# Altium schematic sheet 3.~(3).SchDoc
size 420 x 297 mm
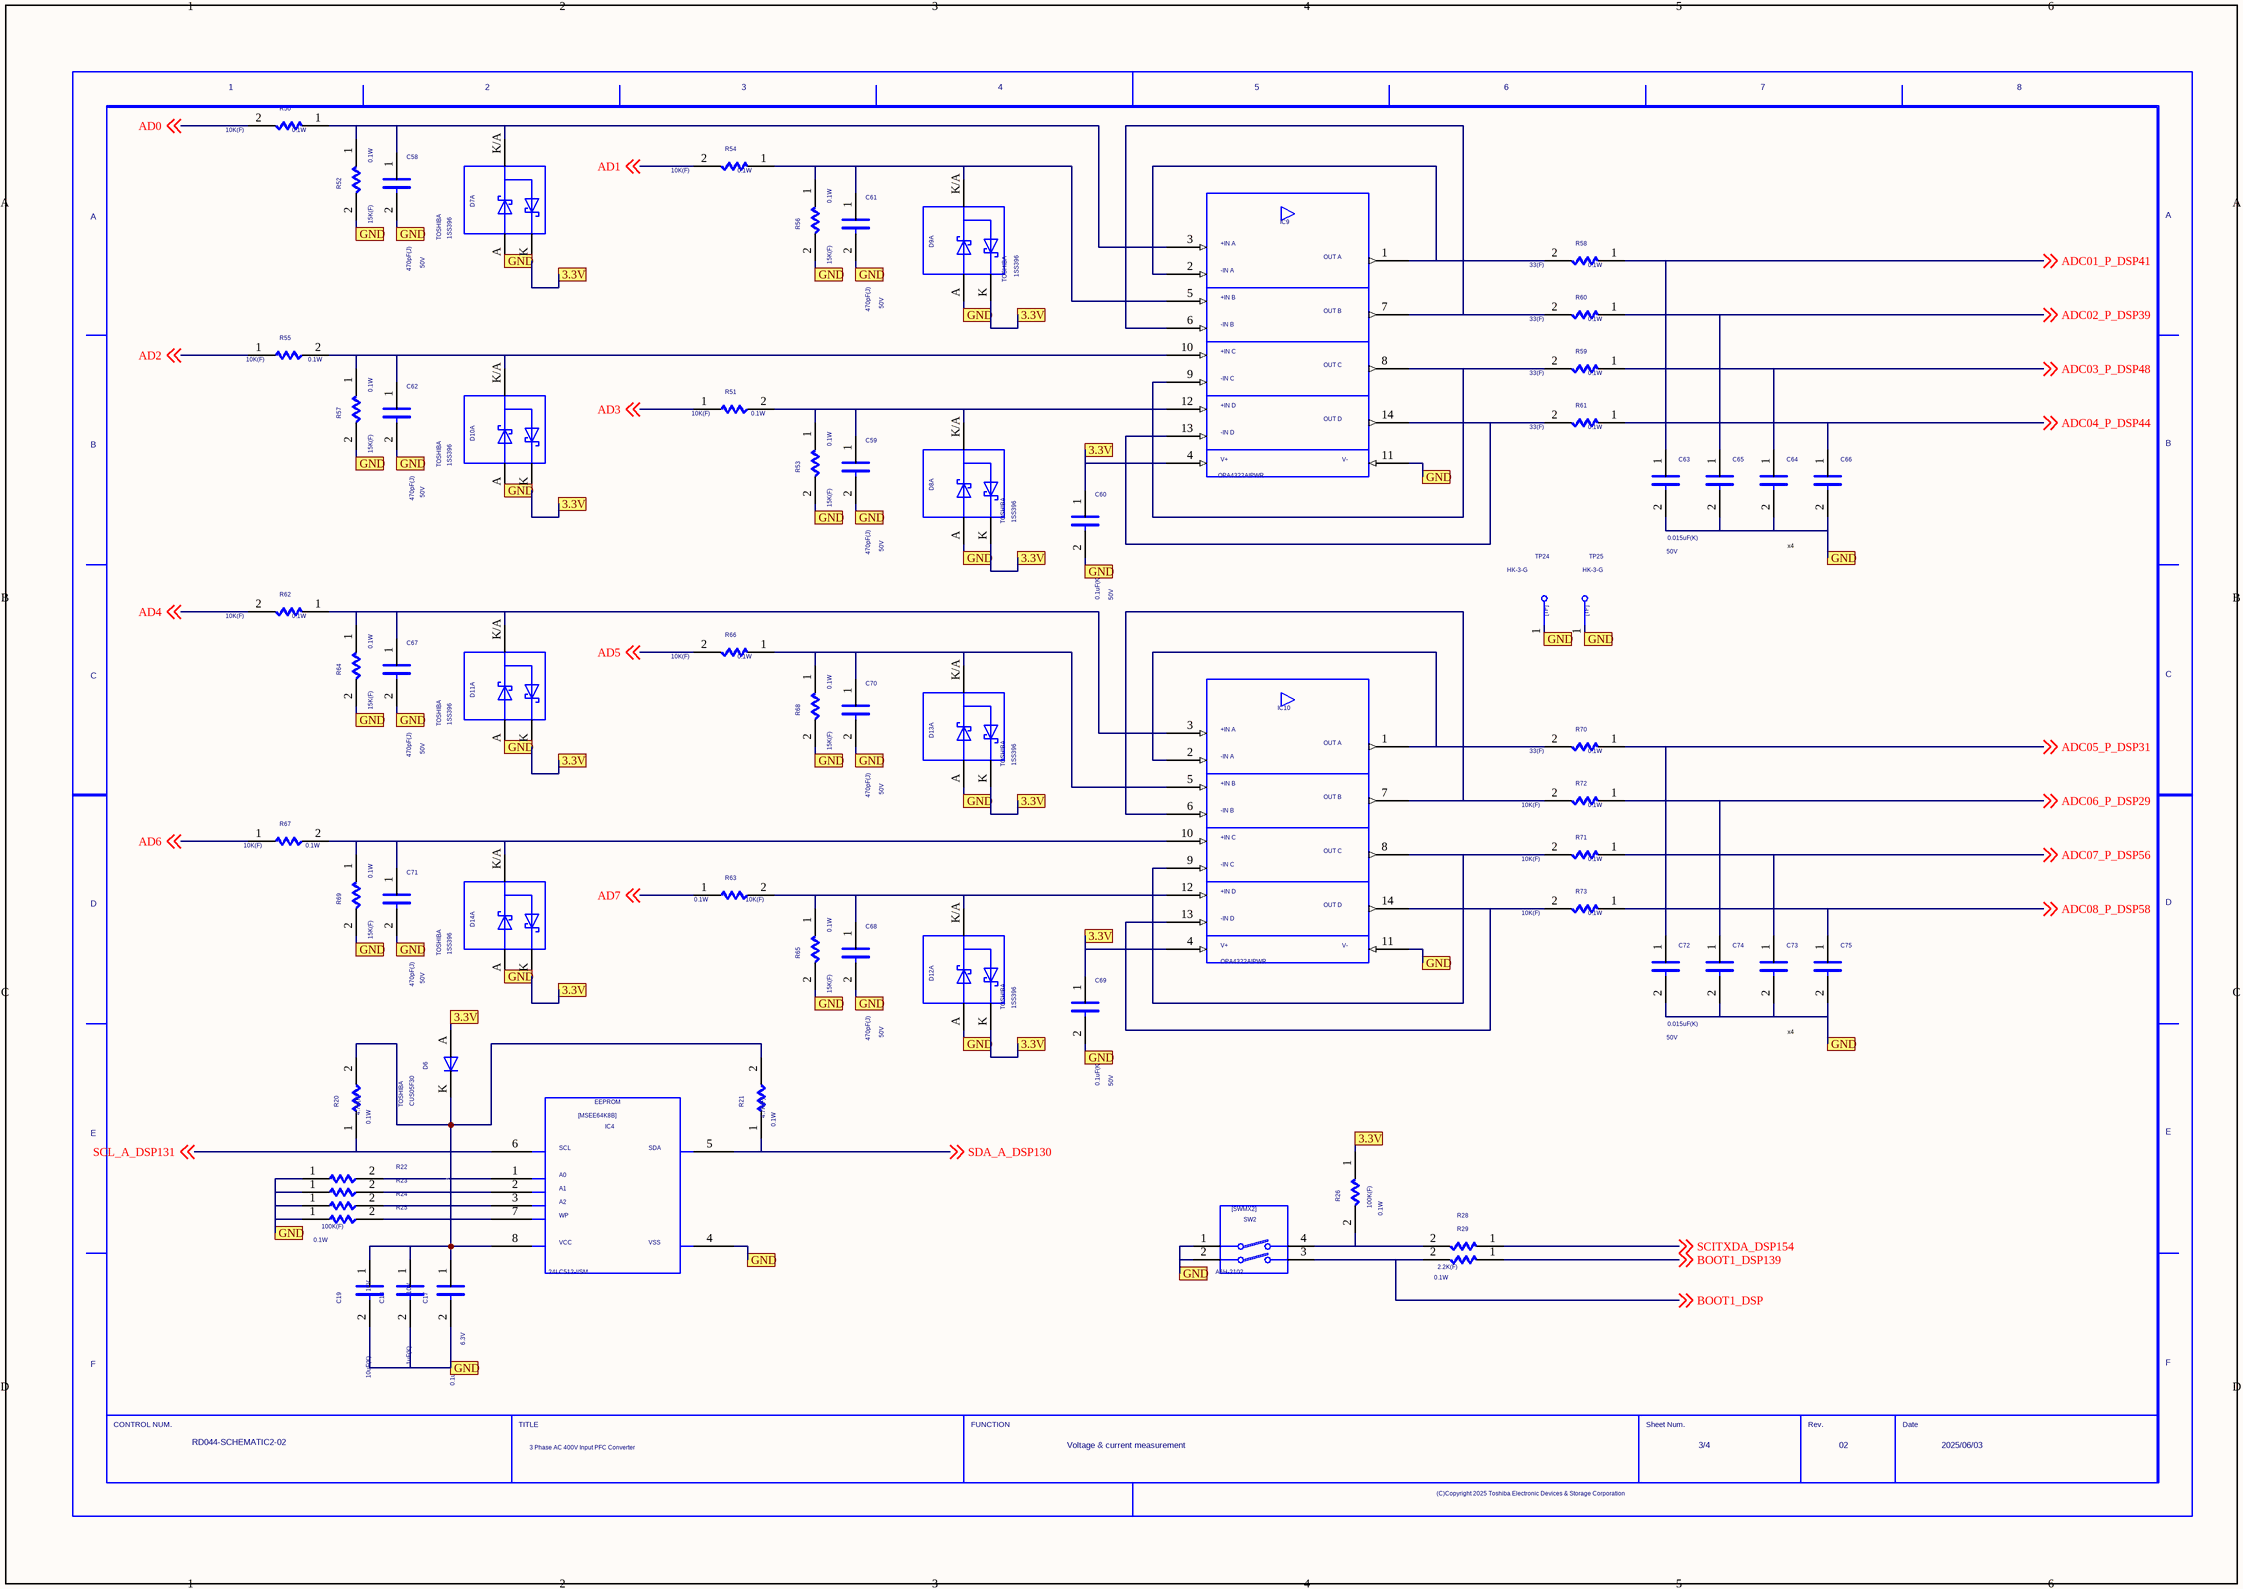
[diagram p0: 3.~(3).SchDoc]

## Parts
C17  VAL1: 0.1uF(K)  VAL2: 6.3V  (hidden comment: C)
C18  VAL1: 1uF(K)  VAL2: 10V  (hidden comment: C)
C19  VAL1: 10uF(K)  VAL2: 10V  (hidden comment: C)
C58  VAL1: 470pF(J)  VAL2: 50V  (hidden comment: C)
C59  VAL1: 470pF(J)  VAL2: 50V  (hidden comment: C)
C60  VAL1: 0.1uF(K)  VAL2: 50V  (hidden comment: C)
C61  VAL1: 470pF(J)  VAL2: 50V  (hidden comment: C)
C62  VAL1: 470pF(J)  VAL2: 50V  (hidden comment: C)
C63  VAL1: 0.015uF(K)  VAL2: 50V  (hidden comment: C)
C64  C  (value not drawn)
C65  C  (value not drawn)
C66  C  (value not drawn)
C67  VAL1: 470pF(J)  VAL2: 50V  (hidden comment: C)
C68  VAL1: 470pF(J)  VAL2: 50V  (hidden comment: C)
C69  VAL1: 0.1uF(K)  VAL2: 50V  (hidden comment: C)
C70  VAL1: 470pF(J)  VAL2: 50V  (hidden comment: C)
C71  VAL1: 470pF(J)  VAL2: 50V  (hidden comment: C)
C72  VAL1: 0.015uF(K)  VAL2: 50V  (hidden comment: C)
C73  C  (value not drawn)
C74  C  (value not drawn)
C75  C  (value not drawn)
D6  USERCOMPTEXT3: TOSHIBA  VAL3: CUS05F30  (hidden comment: DIODE)
D7  USERCOMPTEXT3: TOSHIBA  (hidden comment: 1SS396)  (part A of 3)
D8  USERCOMPTEXT3: TOSHIBA  (hidden comment: 1SS396)  (part A of 3)
D9  USERCOMPTEXT3: TOSHIBA  (hidden comment: 1SS396)  (part A of 3)
D10  USERCOMPTEXT3: TOSHIBA  (hidden comment: 1SS396)  (part A of 3)
D11  USERCOMPTEXT3: TOSHIBA  (hidden comment: 1SS396)  (part A of 3)
D12  USERCOMPTEXT3: TOSHIBA  (hidden comment: 1SS396)  (part A of 3)
D13  USERCOMPTEXT3: TOSHIBA  (hidden comment: 1SS396)  (part A of 3)
D14  USERCOMPTEXT3: TOSHIBA  (hidden comment: 1SS396)  (part A of 3)
IC4  VAL3: 24LC512-I/SM  (hidden comment: MSEE64K8B)
IC9  VAL3: OPA4322AIPWR  (hidden comment: OPA4322A)
IC10  VAL3: OPA4322AIPWR  (hidden comment: OPA4322A)
R20  VAL2: 0.1W  VAL1: 4.7K(F)  (hidden comment: R)
R21  VAL2: 0.1W  VAL1: 4.7K(F)  (hidden comment: R)
R22  R  (value not drawn)
R23  R  (value not drawn)
R24  R  (value not drawn)
R25  VAL2: 0.1W  VAL1: 100K(F)  (hidden comment: R)
R26  VAL2: 0.1W  VAL1: 100K(F)  (hidden comment: R)
R28  R  (value not drawn)
R29  VAL2: 0.1W  VAL1: 2.2K(F)  (hidden comment: R)
R50  VAL2: 0.1W  VAL1: 10K(F)  (hidden comment: R)
R51  VAL2: 0.1W  VAL1: 10K(F)  (hidden comment: R)
R52  VAL2: 0.1W  VAL1: 15K(F)  (hidden comment: R)
R53  VAL2: 0.1W  VAL1: 15K(F)  (hidden comment: R)
R54  VAL2: 0.1W  VAL1: 10K(F)  (hidden comment: R)
R55  VAL2: 0.1W  VAL1: 10K(F)  (hidden comment: R)
R56  VAL2: 0.1W  VAL1: 15K(F)  (hidden comment: R)
R57  VAL2: 0.1W  VAL1: 15K(F)  (hidden comment: R)
R58  VAL2: 0.1W  VAL1: 33(F)  (hidden comment: R)
R59  VAL2: 0.1W  VAL1: 33(F)  (hidden comment: R)
R60  VAL2: 0.1W  VAL1: 33(F)  (hidden comment: R)
R61  VAL2: 0.1W  VAL1: 33(F)  (hidden comment: R)
R62  VAL2: 0.1W  VAL1: 10K(F)  (hidden comment: R)
R63  VAL2: 0.1W  VAL1: 10K(F)  (hidden comment: R)
R64  VAL2: 0.1W  VAL1: 15K(F)  (hidden comment: R)
R65  VAL2: 0.1W  VAL1: 15K(F)  (hidden comment: R)
R66  VAL2: 0.1W  VAL1: 10K(F)  (hidden comment: R)
R67  VAL2: 0.1W  VAL1: 10K(F)  (hidden comment: R)
R68  VAL2: 0.1W  VAL1: 15K(F)  (hidden comment: R)
R69  VAL2: 0.1W  VAL1: 15K(F)  (hidden comment: R)
R70  VAL2: 0.1W  VAL1: 33(F)  (hidden comment: R)
R71  VAL2: 0.1W  VAL1: 10K(F)  (hidden comment: R)
R72  VAL2: 0.1W  VAL1: 10K(F)  (hidden comment: R)
R73  VAL2: 0.1W  VAL1: 10K(F)  (hidden comment: R)
SW2  VAL3: A6H-2102  (hidden comment: SWMX2)
TP24  VAL3: HK-3-G  (hidden comment: TP)
TP25  VAL3: HK-3-G  (hidden comment: TP)
U?  DATE: 2025/06/03  DRAWINGNUMBER: RD044-SCHEMATIC2-02  TITLE: 3 Phase AC 400V Input PFC Converter  FUNCTION: Voltage & current measurement  SHEETNUMBER: 3/4  REVISION: 02  (hidden comment: WAKU_DEF100_2018)

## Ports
3.3V, GND

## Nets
3.3V: C17.2 C18.2 C19.2 C58.2 C59.2 C60.1 C60.2 C61.2 C62.2 C63.2 C64.2 C65.2 C66.2 C67.2 C68.2 C69.1 C69.2 C70.2 C71.2 C72.2 C73.2 C74.2 C75.2 D6.A D7.A D7.K D8.A D8.K D9.A D9.K D10.A D10.K D11.A D11.K D12.A D12.K D13.A D13.K D14.A D14.K IC4.4 IC9.4 IC9.11 IC10.4 IC10.11 R22.1 R23.1 R24.1 R25.1 R26.1 R52.2 R53.2 R56.2 R57.2 R64.2 R65.2 R68.2 R69.2 SW2.1 SW2.2 TP24.1 TP25.1 ; port GND, port 3.3V
AD0: R50.2 ; off-sheet AD0
AD1: R54.2 ; off-sheet AD1
AD2: R55.1 ; off-sheet AD2
AD3: R51.1 ; off-sheet AD3
AD4: R62.2 ; off-sheet AD4
AD5: R66.2 ; off-sheet AD5
AD6: R67.1 ; off-sheet AD6
AD7: R63.1 ; off-sheet AD7
ADC01_P_DSP41: C63.1 R58.1 ; off-sheet ADC01_P_DSP41
ADC02_P_DSP39: C65.1 R60.1 ; off-sheet ADC02_P_DSP39
ADC03_P_DSP48: C64.1 R59.1 ; off-sheet ADC03_P_DSP48
ADC04_P_DSP44: C66.1 R61.1 ; off-sheet ADC04_P_DSP44
ADC05_P_DSP31: C72.1 R70.1 ; off-sheet ADC05_P_DSP31
ADC06_P_DSP29: C74.1 R72.1 ; off-sheet ADC06_P_DSP29
ADC07_P_DSP56: C73.1 R71.1 ; off-sheet ADC07_P_DSP56
ADC08_P_DSP58: C75.1 R73.1 ; off-sheet ADC08_P_DSP58
BOOT1_DSP: R29.2 SW2.3 ; off-sheet BOOT1_DSP
BOOT1_DSP139: R29.1 ; off-sheet BOOT1_DSP139
N16610346: C17.1 C18.1 C19.1 D6.K IC4.8 R20.2 R21.2
N16610376: IC4.1 R22.2
N16610420: IC4.2 R23.2
N16610428: IC4.7 R25.2
N16610486: IC4.3 R24.2
N16610930: R26.2 R28.2 SW2.4
N16624647: C59.1 D8.K/A IC9.12 R51.2 R53.1
N16624651: C58.1 D7.K/A IC9.3 R50.1 R52.1
N16624783: IC9.1 IC9.2 R58.2
N16624799: IC9.13 IC9.14 R61.2
N16625013: C61.1 D9.K/A IC9.5 R54.1 R56.1
N16625021: C62.1 D10.K/A IC9.10 R55.2 R57.1
N16625097: IC9.6 IC9.7 R60.2
N16625113: IC9.8 IC9.9 R59.2
N16625873: C67.1 D11.K/A IC10.3 R62.1 R64.1
N16626013: IC10.1 IC10.2 R70.2
N16626029: IC10.13 IC10.14 R73.2
N16626045: C68.1 D12.K/A IC10.12 R63.2 R65.1
N16626273: C70.1 D13.K/A IC10.5 R66.1 R68.1
N16626281: C71.1 D14.K/A IC10.10 R67.2 R69.1
N16626357: IC10.6 IC10.7 R72.2
N16626365: IC10.8 IC10.9 R71.2
SCITXDA_DSP154: R28.1 ; off-sheet SCITXDA_DSP154
SCL_A_DSP131: IC4.6 R20.1 ; off-sheet SCL_A_DSP131
SDA_A_DSP130: IC4.5 R21.1 ; off-sheet SDA_A_DSP130

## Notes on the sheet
- x4

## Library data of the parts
C17 = C: OriginalSymbolOrigin: (2540,7620); CDBNAME: C-GRM155R70J104KA01D; USERCOMPTEXT1: 1005
C18 = C: OriginalSymbolOrigin: (2540,7620); CDBNAME: C-GRM188R71A105KA61D; USERCOMPTEXT1: 1608
C19 = C: OriginalSymbolOrigin: (2540,7620); CDBNAME: C-GRM188R61A106KE69D; USERCOMPTEXT1: 1608
C58 C59 C61 C62 C67 C68 C70 C71 = C: OriginalSymbolOrigin: (2540,7620); CDBNAME: C-GRM1885C1H471JA01D; USERCOMPTEXT1: 1608
C60 C69 = C: OriginalSymbolOrigin: (2540,7620); CDBNAME: C-GRM188R71H104KA93D; USERCOMPTEXT1: 1608
C63 C72 = C: OriginalSymbolOrigin: (2540,7620); CDBNAME: C-GRM188R11H153KA01D; USERCOMPTEXT1: 1608
C64-C66 C73-C75 = C: VAL1: 0.015uF(K); VAL2: 50V; OriginalSymbolOrigin: (2540,7620); CDBNAME: C-GRM188R11H153KA01D; USERCOMPTEXT1: 1608
D6 = DIODE: SAVEAREA0: -1337,-97,13924,7829; SAVECOUNT: 4; TIME: 14:49:55; UPDATEUSER: cae; UPDATETIME: 13:41:08; OriginalSymbolOrigin: (5080,5080); CDBNAME: D-CUS05F30
D7-D14 = 1SS396: SAVECOUNT: 7; SAVEAREA0: -5465,-437,27678,21425; TIME: 18:51:12; UPDATEUSER: cae; UPDATETIME: 10:39:29; OriginalSymbolOrigin: (5080,17780); CDBNAME: D-1SS396_AK
IC4 = MSEE64K8B: SAVECOUNT: 8; SAVEAREA0: -9998,-458,55119,39162; TIME: 10:18:07; UPDATEUSER: 19990028; UPDATETIME: 09:15:23; OriginalSymbolOrigin: (7620,35560); MAXGCOUNT: 1; CDBNAME: IC-24LC512-I_SM; ADSCNVFLAG: ON
IC9 IC10 = OPA4322A: SAVECOUNT: 28; SAVEAREA0: -34439,-609,80338,59004; TIME: 15:40:02; UPDATEUSER: cae; UPDATETIME: 16:49:13; OriginalSymbolOrigin: (7620,55880); CDBNAME: IC-OPA4322AIPWR
R20 R21 = R: OriginalSymbolOrigin: (5080,5080); CDBNAME: R-ERJ3EKF4701V; USERCOMPTEXT1: 1608
R22-R24 = R: VAL2: 0.1W; VAL1: 100K(F); OriginalSymbolOrigin: (5080,5080); CDBNAME: R-ERJ3EKF1003V; USERCOMPTEXT1: 1608
R25 R26 = R: OriginalSymbolOrigin: (5080,5080); CDBNAME: R-ERJ3EKF1003V; USERCOMPTEXT1: 1608
R28 = R: VAL2: 0.1W; VAL1: 2.2K(F); OriginalSymbolOrigin: (5080,5080); CDBNAME: R-ERJ3EKF2201V; USERCOMPTEXT1: 1608
R29 = R: OriginalSymbolOrigin: (5080,5080); CDBNAME: R-ERJ3EKF2201V; USERCOMPTEXT1: 1608
R50 R51 R54 R55 R62 R63 R66 R67 = R: OriginalSymbolOrigin: (5080,5080); CDBNAME: R-ERJ3EKF1002V; USERCOMPTEXT1: 1608
R52 R53 R56 R57 R64 R65 R68 R69 = R: OriginalSymbolOrigin: (5080,5080); CDBNAME: R-ERJ3EKF1502V; USERCOMPTEXT1: 1608
R58-R61 R70-R73 = R: OriginalSymbolOrigin: (5080,5080); CDBNAME: R-ERJ3EKF33R0V; USERCOMPTEXT1: 1608
SW2 = SWMX2: OriginalSymbolOrigin: (5080,15240); CDBNAME: SW-A6H-2102
TP24 TP25 = TP: TIME: 16:12:21; UPDATEUSER: fukuda-y; UPDATETIME: 16:18:11; SAVECOUNT: 2; SAVEAREA0: -242,-92,12810,7836; OriginalSymbolOrigin: (0,7620); CDBNAME: TP-HK-3-G
U? = WAKU_DEF100_2018: PLOTTIME: HH:MM; SAVEAREA0: -45080,-4508,463680,304612; TIME: 13:54:34; UPDATEUSER: e5025010; UPDATETIME: 16:01:41; SAVECOUNT: 4; OriginalSymbolOrigin: (10160,284480); SHTSAVECOUNT: 6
